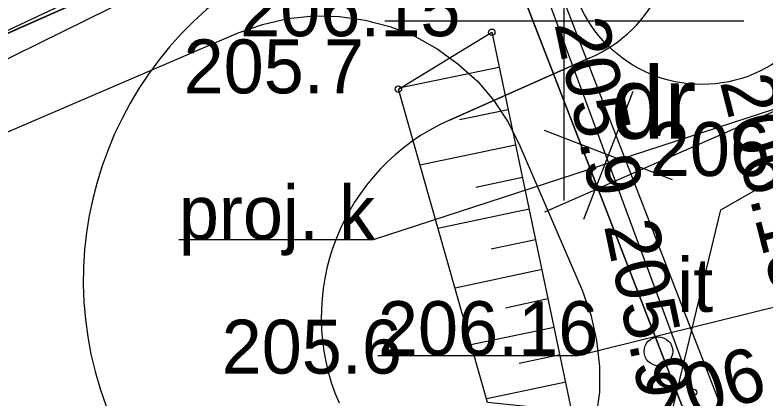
# Model space of a CAD drawing. Extents: x 6512606 to 6513006, y 6022524 to 6022728.
# Drawn here: x 6512842.35 to 6512852.81, y 6022594.74 to 6022600.08 of the extents above; entities that cross this region are included whole.
import ezdxf

# ---------------------------------------------------------------- set-up
doc = ezdxf.new("R2010")
doc.units = 0
for name, color, linetype in [('000 Inne (niezydentyfikowane)', 7, 'Continuous'), ('210-oznaczenie konturu użytku gruntowego', 7, 'Continuous'), ('217-kontur klasyfikacyjny', 7, 'Continuous'), ('218-kontur użytku gruntowego', 7, 'Continuous'), ('219-działka ewidencyjna', 7, 'Continuous'), ('4', 7, 'Continuous'), ('6', 7, 'Continuous'), ('Default', 7, 'Continuous'), ('inny obiekt zagospodarowania terenu', 7, 'Continuous'), ('inny obiekt zagospodarowania terenu-Atr17', 7, 'Continuous'), ('kolor_chodnik', 7, 'Continuous'), ('kolor_kostka_bet', 7, 'Continuous'), ('kolor_sc_rowerowa', 7, 'Continuous'), ('maxp_kan_deszczowa', 7, 'Continuous'), ('maxp_kraw_nawierzchni', 7, 'Continuous'), ('maxp_likwidacje', 7, 'Continuous'), ('maxp_obrzeże', 7, 'Continuous'), ('maxp_ramka_2', 7, 'Continuous'), ('ogrodzenie trwałe', 7, 'Continuous'), ('pikieta naturalna', 7, 'Continuous'), ('pikieta naturalna-Atr2', 7, 'Continuous'), ('pikieta sztuczna-Atr2', 7, 'Continuous'), ('przewód kanalizacyjny - projektowany lub w budowie (linia) - ob. projektowany', 7, 'Continuous'), ('przewód kanalizacyjny - projektowany lub w budowie (linia) - ob. projektowany-Atr1', 7, 'Continuous'), ('punkt o określonej wysokości (sieć telekomunikacyjna)-Atr2', 7, 'Continuous'), ('skarpa nieumocniona', 7, 'Continuous'), ('urządzenie techniczne projektowane lub w budowie (sieć kanalizacyjna) - powierzchnia - ob. projektowany', 7, 'Continuous')]:
    doc.layers.add(name, color=color, linetype=linetype)

# ---------------------------------------------------------------- blocks, each defined once
blk = doc.blocks.new('PW01')
at = {"layer": 'Default'}
blk.add_circle((0, 0), 0.45, dxfattribs=at)
blk = doc.blocks.new('US25')
at = {"layer": 'Default'}
blk.add_circle((0, 0), 2, dxfattribs=at)

msp = doc.modelspace()

# ---------------------------------------------------------------- linework, layer by layer
at = {"layer": '000 Inne (niezydentyfikowane)'}
for points in [[(6512849.09, 6022599.35), (6512847.7, 6022599.06)], [(6512849.22, 6022598.76), (6512848.54, 6022598.62)], [(6512849.32, 6022598.27), (6512847.99, 6022597.99)], [(6512849.42, 6022597.82), (6512848.77, 6022597.68)], [(6512849.51, 6022597.38), (6512848.24, 6022597.11)], [(6512849.6, 6022596.95), (6512848.98, 6022596.82)], [(6512849.69, 6022596.54), (6512848.48, 6022596.28)], [(6512849.77, 6022596.13), (6512849.18, 6022596)], [(6512849.86, 6022595.73), (6512848.7, 6022595.49)], [(6512849.94, 6022595.35), (6512849.37, 6022595.23)], [(6512850.02, 6022594.97), (6512848.92, 6022594.74)]]:
    msp.add_lwpolyline(points, dxfattribs=at)
at = {"layer": '217-kontur klasyfikacyjny'}
for points in [[(6512811.09, 6022586.02), (6512848.55, 6022602.62)], [(6512848.55, 6022602.62), (6512811.09, 6022586.02)], [(6512855.78, 6022583.95), (6512848.55, 6022602.62)]]:
    msp.add_lwpolyline(points, dxfattribs=at)
at = {"layer": '218-kontur użytku gruntowego'}
for points in [[(6512811.09, 6022586.02), (6512848.55, 6022602.62)], [(6512848.55, 6022602.62), (6512811.09, 6022586.02)], [(6512848.55, 6022602.62), (6512855.78, 6022583.95)], [(6512855.78, 6022583.95), (6512848.55, 6022602.62)]]:
    msp.add_lwpolyline(points, dxfattribs=at)
at = {"layer": '219-działka ewidencyjna'}
for points in [[(6512811.09, 6022586.02), (6512848.55, 6022602.62)], [(6512855.78, 6022583.95), (6512848.55, 6022602.62)]]:
    msp.add_lwpolyline(points, dxfattribs=at)
at = {"layer": '4'}
for points in [[(6512811.09, 6022586.02), (6512848.55, 6022602.62)], [(6512855.78, 6022583.95), (6512848.55, 6022602.62)]]:
    msp.add_lwpolyline(points, dxfattribs=at)
at = {"layer": '6'}
msp.add_circle((6512851.916, 6022600.973), 1.859, dxfattribs=at)
at = {"layer": 'Default'}
for p, q in [((6512850, 6022597.5), (6512850, 6022602.5)), ((6512847.5, 6022600), (6512852.5, 6022600))]:
    msp.add_line(p, q, dxfattribs=at)
at = {"layer": 'kolor_chodnik'}
msp.add_line((6512850.356, 6022599.483), (6512848.401, 6022598.617), dxfattribs=at)
for centre, radius, start, end in [((6512849.546, 6022601.311), 2, 293.9, 14.2544), ((6512849.617, 6022595.874), 3, 113.9, 203.397)]:
    msp.add_arc(centre, radius, start, end, dxfattribs=at)
at = {"layer": 'kolor_kostka_bet'}
msp.add_line((6512820.033, 6022589.983), (6512848.55, 6022602.62), dxfattribs=at)
msp.add_lwpolyline([(6512848.55, 6022602.62), (6512826.343, 6022592.779), (6512820.033, 6022589.983)], dxfattribs=at)
msp.add_arc((6512848.305, 6022596.386), 5, 113.9, 203.397, dxfattribs=at)
at = {"layer": 'kolor_sc_rowerowa'}
msp.add_line((6512848.401, 6022598.617), (6512850.356, 6022599.483), dxfattribs=at)
for centre, radius, start, end in [((6512849.546, 6022601.311), 2, 293.9, 14.2544), ((6512848.305, 6022596.386), 5, 113.9, 203.397), ((6512849.617, 6022595.874), 3, 113.9, 203.397)]:
    msp.add_arc(centre, radius, start, end, dxfattribs=at)
at = {"layer": 'maxp_kan_deszczowa'}
for points in [[(6512855.131, 6022585.797), (6512853.495, 6022589.851), (6512851.482, 6022595.049), (6512848.64, 6022602.387)], [(6512844.992, 6022600.824), (6512840.035, 6022598.38), (6512839.288, 6022595.519), (6512840.706, 6022591.84), (6512832.721, 6022588.268), (6512829.602, 6022587.385)]]:
    msp.add_lwpolyline(points, dxfattribs=at)
at = {"layer": 'maxp_kraw_nawierzchni'}
msp.add_line((6512848.401, 6022598.617), (6512850.356, 6022599.483), dxfattribs=at)
for centre, radius, start, end in [((6512849.546, 6022601.311), 2, 293.9, 14.2544), ((6512849.617, 6022595.874), 3, 113.9, 203.397)]:
    msp.add_arc(centre, radius, start, end, dxfattribs=at)
at = {"layer": 'maxp_likwidacje'}
for p, q in [((6512850.271, 6022597.239), (6512850.958, 6022599.02)), ((6512851.505, 6022597.786), (6512849.724, 6022598.473))]:
    msp.add_line(p, q, dxfattribs=at)
at = {"layer": 'maxp_obrzeże'}
msp.add_arc((6512848.305, 6022596.386), 5, 113.9, 203.397, dxfattribs=at)
at = {"layer": 'maxp_ramka_2'}
msp.add_line((6512848.827, 6022603.29), (6512856.423, 6022583.675), dxfattribs=at)
at = {"layer": 'ogrodzenie trwałe'}
for points in [[(6512847.46, 6022602.32), (6512839.9, 6022598.76), (6512838.38, 6022602.97)], [(6512851.8, 6022594.83), (6512849.78, 6022600.29)]]:
    msp.add_lwpolyline(points, dxfattribs=at)
at = {"layer": 'przewód kanalizacyjny - projektowany lub w budowie (linia) - ob. projektowany'}
for points in [[(6512849.73, 6022597.34), (6512856.94, 6022600.51)], [(6512851.27, 6022593.61), (6512852.18, 6022597.37), (6512857.2, 6022600.23)]]:
    msp.add_lwpolyline(points, dxfattribs=at)
at = {"layer": 'przewód kanalizacyjny - projektowany lub w budowie (linia) - ob. projektowany-Atr1'}
msp.add_lwpolyline([(6512853.14, 6022598.84), (6512847.34, 6022596.95), (6512844.634, 6022596.95)], dxfattribs=at)
at = {"layer": 'punkt o określonej wysokości (sieć telekomunikacyjna)-Atr2'}
msp.add_lwpolyline([(6512854.17, 6022596.32), (6512850.19, 6022595.34), (6512847.405, 6022595.34)], dxfattribs=at)
at = {"layer": 'skarpa nieumocniona'}
msp.add_lwpolyline([(6512847.69, 6022599.05), (6512848.99, 6022599.84), (6512850.1, 6022594.57), (6512848.93, 6022594.69)], close=True, dxfattribs=at)
msp.add_lwpolyline([(6512847.69, 6022599.05), (6512848.99, 6022599.84), (6512850.1, 6022594.57), (6512848.93, 6022594.69)], close=True, dxfattribs=at)
at = {"layer": 'urządzenie techniczne projektowane lub w budowie (sieć kanalizacyjna) - powierzchnia - ob. projektowany'}
msp.add_lwpolyline([(6512813.61, 6022586.15), (6512845.46, 6022599.83), (6512845.8, 6022599.95), (6512846.15, 6022600.03), (6512846.51, 6022600.07), (6512846.87, 6022600.06), (6512847.23, 6022600.01), (6512847.57, 6022599.92), (6512847.91, 6022599.79), (6512848.23, 6022599.61), (6512848.52, 6022599.4), (6512848.79, 6022599.16), (6512849.02, 6022598.89), (6512849.22, 6022598.59), (6512849.38, 6022598.26), (6512850.25, 6022596.25), (6512850.37, 6022595.91), (6512850.45, 6022595.55), (6512850.49, 6022595.19), (6512850.49, 6022594.83), (6512850.44, 6022594.48)], dxfattribs=at)

# ---------------------------------------------------------------- block references
at = {"layer": 'inny obiekt zagospodarowania terenu', "xscale": 0.1, "yscale": 0.10000000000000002}
msp.add_blockref('US25', (6512851.31, 6022595.4), dxfattribs=at)
at = {"layer": 'pikieta naturalna', "xscale": 0.1, "yscale": 0.10000000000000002}
for p in [(6512848.99, 6022599.84), (6512847.69, 6022599.05), (6512851.8, 6022594.83)]:
    msp.add_blockref('PW01', p, dxfattribs=at)

# ---------------------------------------------------------------- texts
at = {"layer": '210-oznaczenie konturu użytku gruntowego'}
msp.add_text('dr', height=1, dxfattribs=at).set_placement((6512850.65, 6022598.36))
at = {"layer": 'inny obiekt zagospodarowania terenu-Atr17'}
msp.add_text('it', height=0.75, dxfattribs=at).set_placement((6512851.57, 6022595.95))
at = {"layer": 'pikieta naturalna-Atr2'}
for p in [(6512849.86, 6022599.96), (6512850.55, 6022597.15)]:
    msp.add_text('205.9', height=0.75, rotation=281.894, dxfattribs=at).set_placement(p)
for s, p in [('205.7', (6512844.7, 6022598.99)), ('206.1', (6512851.19, 6022597.84)), ('205.6', (6512845.23, 6022595.09))]:
    msp.add_text(s, height=0.75, dxfattribs=at).set_placement(p)
at = {"layer": 'pikieta sztuczna-Atr2'}
msp.add_text('206.15', height=0.75, dxfattribs=at).set_placement((6512845.487, 6022599.785))
for s, rotation, p in [('206.15', 284.357, (6512852.162, 6022599.15)), ('206.14', 17.103, (6512851.261, 6022594.281))]:
    msp.add_text(s, height=0.75, rotation=rotation, dxfattribs=at).set_placement(p)
at = {"layer": 'przewód kanalizacyjny - projektowany lub w budowie (linia) - ob. projektowany-Atr1'}
msp.add_text('proj. k', height=0.75, dxfattribs=at).set_placement((6512844.634, 6022596.958))
at = {"layer": 'punkt o określonej wysokości (sieć telekomunikacyjna)-Atr2'}
msp.add_text('206.16', height=0.75, dxfattribs=at).set_placement((6512847.405, 6022595.348))

doc.saveas('drawing.dxf')
